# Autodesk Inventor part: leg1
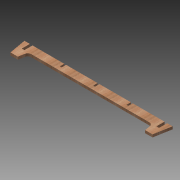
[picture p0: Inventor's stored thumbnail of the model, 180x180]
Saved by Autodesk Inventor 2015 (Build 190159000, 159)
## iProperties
Created: 2015-04
Part Number: leg1
Material: Wood (Birch)
Document SubType Name: Modeling
Designer: sungeun
Density: 0.55 g/cm^3
Appearance: Birch - Natural Polished
Author: sungeun
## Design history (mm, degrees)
sketch "Sketch1"
  geometry: L1 (-959.445, 0)-(-1000, 230); L2 (-1000, 230)-(0, 230); L3 (-959.445, 0)-(-859.445, 0); L4 (-859.445, 0)-(-838.286, 120); L5 (-838.286, 120)-(0, 120); L6 (0, 230)-(0, 120); L7 (1000, 230)-(0, 230); L8 (959.445, 0)-(1000, 230); L9 (859.445, 0)-(838.286, 120); L10 (838.286, 120)-(0, 120); L11 (959.445, 0)-(859.445, 0); 3 further points
  constraints: 22 end point, 4 symmetric about line, 3 horizontal, 1 coincident, 1 horizontal alignment, 1 midpoint, 1 vertical, 1 vertical alignment
  dimensions: "depth" = 1000 distance of L1.end L2.end; "height" = 230 distance from line of point (0, 0) L2; "d2" = 80 deg angle of L2 L1; "d3" = 100 distance of L1.start L3.end; "d4" = 120 vertical distance of L3.end L4.end; "d5" = 100 deg angle of L3 L4; "d20" = 909.44479 distance of point (0, 0) point (-909.445, 0) (derived)
extrude "Extrusion1" new body sketch "Sketch1" distance "d6" = 36 (= 3 x thickness); taper "d7" = 0 deg
sketch "Sketch2"
  geometry: L1 (-927.445, 230)-(-891.445, 230); L2 (-891.445, 230)-(-891.445, 120); L3 (-891.445, 120)-(-927.445, 120); L4 (-927.445, 120)-(-927.445, 230); L5 (-859.445, 0)-(-959.445, 0) reference; L6 (0, 230)-(0, 0); L7 (927.445, 230)-(891.445, 230); L8 (891.445, 230)-(891.445, 120); L9 (927.445, 120)-(927.445, 230); L10 (891.445, 120)-(927.445, 120); 3 further points
  constraints: 18 end point, 5 symmetric about line, 2 midpoint, 2 parallel, 1 horizontal, 1 perpendicular, 1 vertical, 1 vertical alignment
  dimensions: "d8" = 110 distance of L1.end L2.end; "d9" = 36 distance of L2.end L3.end (= 3 x thickness); "d10" = 120 distance between parallel lines of L5 L3
extrude "Extrusion2" cut sketch "Sketch2" stored distance "d11" = 0; taper "d12" = 0 deg
sketch "Sketch3"
  geometry: L1 (-891.445, 230)-(891.445, 230) reference; L2 (-12, 230)-(12, 230); L3 (12, 230)-(12, 170); L4 (12, 170)-(-12, 170); L5 (-12, 170)-(-12, 230); L6 (-462, 230)-(-438, 230); L7 (-438, 230)-(-438, 170); L8 (-438, 170)-(-462, 170); L9 (-462, 170)-(-462, 230); L10 (0, 230)-(0, 170); L11 (462, 230)-(438, 230); L12 (438, 230)-(438, 170); L13 (438, 170)-(462, 170); L14 (462, 170)-(462, 230); 3 further points
  constraints: 26 end point, 5 parallel, 5 symmetric about line, 3 midpoint, 2 horizontal, 2 perpendicular, 2 point on line, 1 vertical alignment
  dimensions: "d13" = 60 distance of L2.end L3.end; "d14" = 24 distance of L3.end L4.end (= 2 x thickness); "d15" = 60 distance of L6.end L7.end (= d13); "d16" = 24 distance of L7.end L8.end (= d14); "d17" = 450 distance of L10.end point (-450, 170)
extrude "Extrusion3" cut sketch "Sketch3" stored distance "d18" = 10; taper "d19" = 0 deg
fillet "Fillet1" dims "d21" = 50
body "Solid1"
other parameters: "thickness" = 12 [user parameter; used in 3 equation terms]
